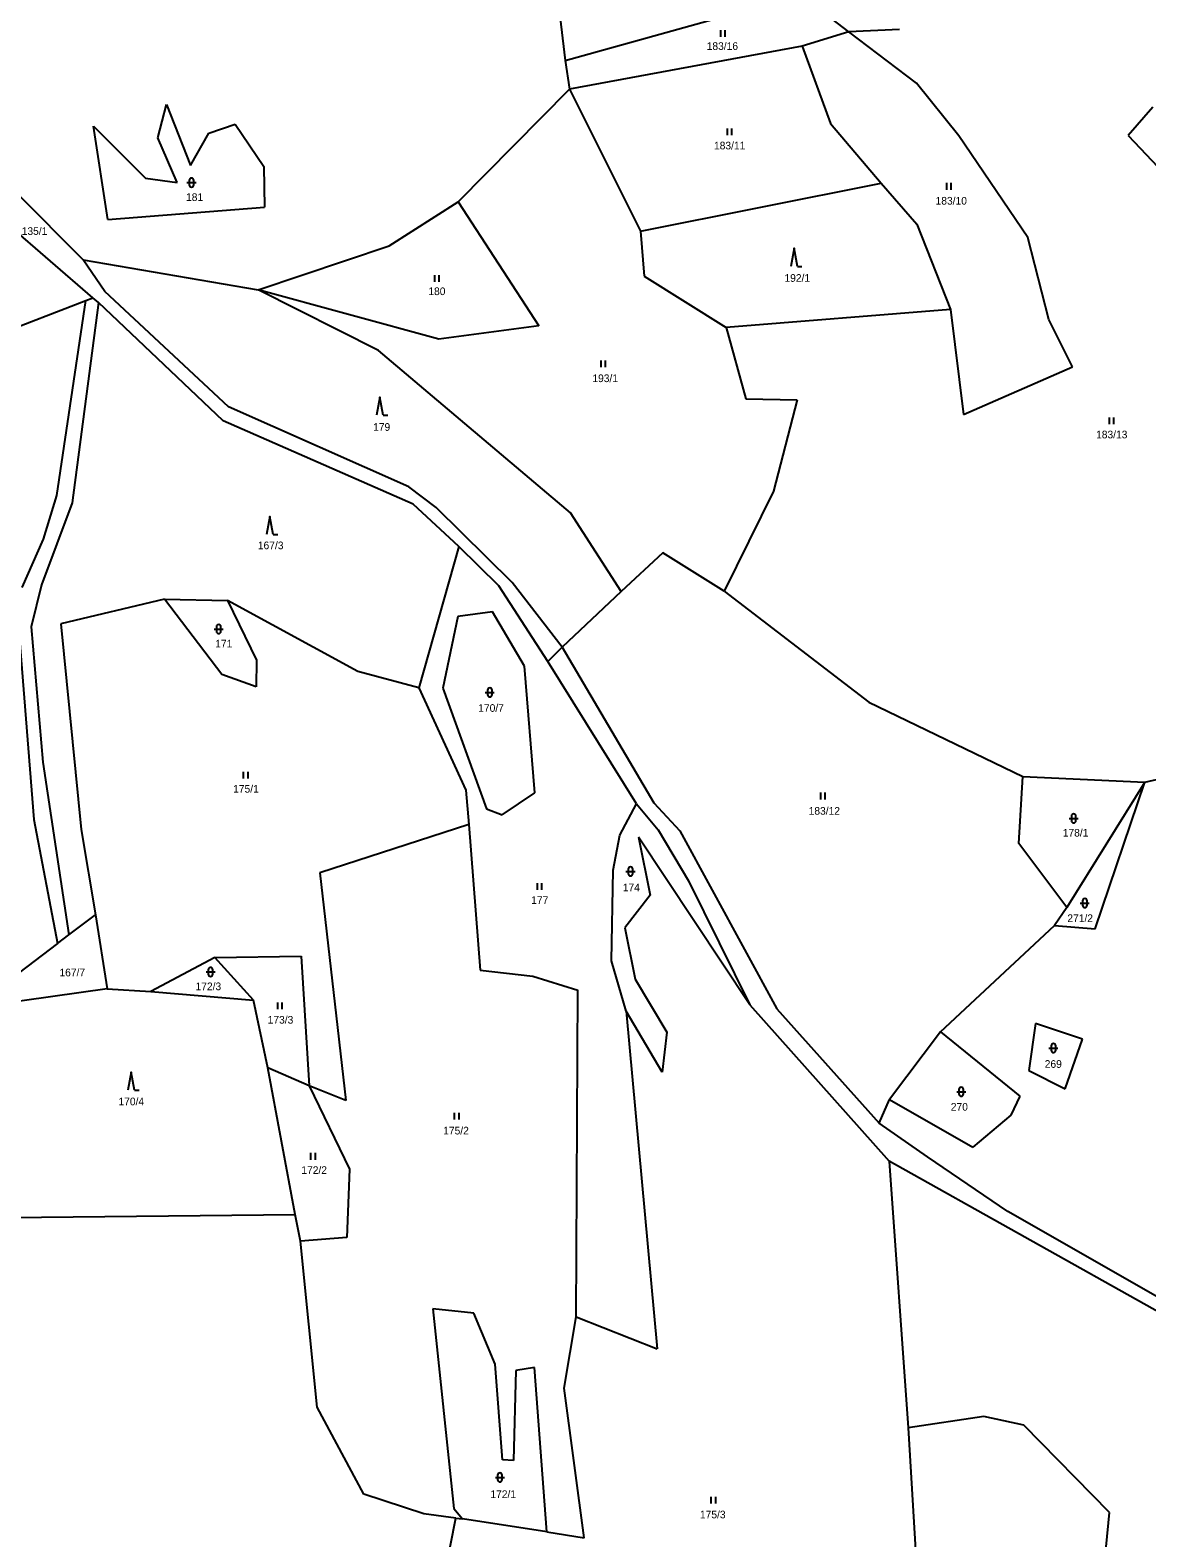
# Model space of a CAD drawing. Extents: x -765428 to -762163, y -1107632 to -1104975.
# Drawn here: x -763268.9 to -763021.2, y -1106469 to -1106134.4 of the extents above; entities that cross this region are included whole.
import ezdxf
from ezdxf.enums import TextEntityAlignment as Align

# ---------------------------------------------------------------- set-up
doc = ezdxf.new("R2010")
doc.units = 0
doc.header["$LTSCALE"] = 0.68
doc.layers.add('1', color=7, linetype='Continuous', lineweight=25)
doc.layers.add('3', color=7, linetype='Continuous', lineweight=25)
doc.layers.add('2', color=7, linetype='Continuous')

msp = doc.modelspace()

# ---------------------------------------------------------------- linework, layer by layer
at = {"layer": '1'}
for p, q in [((-763155.05, -1106100.23), (-763150.2, -1106141.11)), ((-763150.2, -1106141.11), (-763097.96, -1106126.56)), ((-763087.29, -1106134.78), (-763097.96, -1106126.56)), ((-763087.29, -1106134.78), (-763097.65, -1106137.98)), ((-763076.02, -1106134.23), (-763087.29, -1106134.78)), ((-763072.26, -1106146.15), (-763087.29, -1106134.78)), ((-763097.65, -1106137.98), (-763149.26, -1106147.51)), ((-763097.65, -1106137.98), (-763091.31, -1106155.08)), ((-763150.2, -1106141.11), (-763149.26, -1106147.51)), ((-763062.86, -1106157.85), (-763072.26, -1106146.15)), ((-763173.94, -1106172.46), (-763149.26, -1106147.51)), ((-763149.26, -1106147.51), (-763133.47, -1106179.02)), ((-763240.57, -1106158.31), (-763238.65, -1106150.92)), ((-763238.65, -1106150.92), (-763233.33, -1106164.42)), ((-763019.8, -1106151.45), (-763025.33, -1106157.75)), ((-763254.84, -1106155.68), (-763243.34, -1106167.26)), ((-763251.65, -1106176.42), (-763254.84, -1106155.68)), ((-763229.28, -1106157.25), (-763223.39, -1106155.26)), ((-763223.39, -1106155.26), (-763217.07, -1106164.63)), ((-763091.31, -1106155.08), (-763080.07, -1106168.32)), ((-763236.31, -1106168.18), (-763240.57, -1106158.31)), ((-763233.33, -1106164.42), (-763229.28, -1106157.25)), ((-763047.58, -1106180.39), (-763062.86, -1106157.85)), ((-763025.33, -1106157.75), (-763017.35, -1106166.16)), ((-763217.07, -1106164.63), (-763216.92, -1106173.65)), ((-763243.34, -1106167.26), (-763236.31, -1106168.18)), ((-763133.47, -1106179.02), (-763080.07, -1106168.32)), ((-763080.07, -1106168.32), (-763072.22, -1106177.47)), ((-763257.11, -1106185.37), (-763271.76, -1106170.68)), ((-763189.25, -1106182.29), (-763173.94, -1106172.46)), ((-763173.94, -1106172.46), (-763156.06, -1106200.02)), ((-763251.65, -1106176.42), (-763216.92, -1106173.65)), ((-763255.03, -1106193.78), (-763273.81, -1106177.51)), ((-763133.47, -1106179.02), (-763132.69, -1106189.01)), ((-763072.22, -1106177.47), (-763064.74, -1106196.39)), ((-763218.32, -1106192.01), (-763189.25, -1106182.29)), ((-763042.93, -1106198.59), (-763047.58, -1106180.39)), ((-763252.37, -1106192.42), (-763257.11, -1106185.37)), ((-763257.11, -1106185.37), (-763218.32, -1106192.01)), ((-763132.69, -1106189.01), (-763114.5, -1106200.41)), ((-763224.9, -1106218.02), (-763252.37, -1106192.42)), ((-763191.62, -1106205.5), (-763218.32, -1106192.01)), ((-763178.21, -1106202.95), (-763218.32, -1106192.01)), ((-763282.95, -1106204.58), (-763256.59, -1106194.39)), ((-763263.02, -1106237.7), (-763256.59, -1106194.39)), ((-763253.74, -1106194.87), (-763259.6, -1106239.31)), ((-763256.59, -1106194.39), (-763255.03, -1106193.78)), ((-763253.74, -1106194.87), (-763255.03, -1106193.78)), ((-763226.06, -1106221.07), (-763253.74, -1106194.87)), ((-763064.74, -1106196.39), (-763114.5, -1106200.41)), ((-763064.74, -1106196.39), (-763061.8, -1106219.73)), ((-763037.65, -1106209.11), (-763042.93, -1106198.59)), ((-763156.06, -1106200.02), (-763178.21, -1106202.95)), ((-763114.5, -1106200.41), (-763110.11, -1106216.25)), ((-763149.03, -1106241.5), (-763191.62, -1106205.5)), ((-763061.8, -1106219.73), (-763037.65, -1106209.11)), ((-763110.11, -1106216.25), (-763098.72, -1106216.45)), ((-763098.72, -1106216.45), (-763103.95, -1106236.69)), ((-763184.89, -1106235.72), (-763224.9, -1106218.02)), ((-763183.94, -1106239.57), (-763226.06, -1106221.07)), ((-763178.86, -1106240.37), (-763184.89, -1106235.72)), ((-763103.95, -1106236.69), (-763114.94, -1106258.94)), ((-763259.6, -1106239.31), (-763266.4, -1106257.48)), ((-763265.98, -1106247.33), (-763263.02, -1106237.7)), ((-763173.79, -1106248.97), (-763183.94, -1106239.57)), ((-763161.99, -1106256.99), (-763178.86, -1106240.37)), ((-763137.77, -1106259), (-763149.03, -1106241.5)), ((-763270.65, -1106258.08), (-763265.98, -1106247.33)), ((-763173.79, -1106248.97), (-763182.64, -1106280.34)), ((-763164.9, -1106257.73), (-763173.79, -1106248.97)), ((-763128.56, -1106250.38), (-763137.77, -1106259)), ((-763114.94, -1106258.94), (-763128.56, -1106250.38)), ((-763266.4, -1106257.48), (-763268.66, -1106266.83)), ((-763154.03, -1106274.53), (-763164.9, -1106257.73)), ((-763150.89, -1106271.3), (-763161.99, -1106256.99)), ((-763137.77, -1106259), (-763150.89, -1106271.3)), ((-763114.94, -1106258.94), (-763082.87, -1106283.53)), ((-763239.13, -1106260.71), (-763262.07, -1106266.13)), ((-763239.13, -1106260.71), (-763225.12, -1106260.97)), ((-763226.38, -1106277.4), (-763239.13, -1106260.71)), ((-763196.21, -1106276.75), (-763225.12, -1106260.97)), ((-763225.12, -1106260.97), (-763218.72, -1106274.19)), ((-763166.36, -1106263.48), (-763174.01, -1106264.52)), ((-763159.21, -1106275.53), (-763166.36, -1106263.48)), ((-763271.65, -1106264.9), (-763268.06, -1106309.55)), ((-763268.66, -1106266.83), (-763266.06, -1106296.83)), ((-763262.07, -1106266.13), (-763257.62, -1106311.79)), ((-763174.01, -1106264.52), (-763177.36, -1106280.42)), ((-763154.03, -1106274.53), (-763150.89, -1106271.3)), ((-763150.89, -1106271.3), (-763130.53, -1106305.89)), ((-763218.72, -1106274.19), (-763218.8, -1106280.14)), ((-763182.64, -1106280.34), (-763196.21, -1106276.75)), ((-763156.95, -1106303.63), (-763159.21, -1106275.53)), ((-763134.35, -1106306.07), (-763154.03, -1106274.53)), ((-763218.8, -1106280.14), (-763226.38, -1106277.4)), ((-763182.64, -1106280.34), (-763172.26, -1106303.06)), ((-763177.36, -1106280.42), (-763167.65, -1106307.24)), ((-763082.87, -1106283.53), (-763048.67, -1106300.02)), ((-763266.06, -1106296.83), (-763260.29, -1106335.2)), ((-763049.56, -1106314.94), (-763048.67, -1106300.02)), ((-763048.67, -1106300.02), (-763021.57, -1106301.33)), ((-763021.57, -1106301.33), (-763011.94, -1106299.02)), ((-763172.26, -1106303.06), (-763171.59, -1106310.7)), ((-763164.15, -1106308.58), (-763156.95, -1106303.63)), ((-763021.57, -1106301.33), (-763038.92, -1106329.08)), ((-763032.65, -1106333.85), (-763021.57, -1106301.33)), ((-763138.06, -1106313.08), (-763134.35, -1106306.07)), ((-763134.35, -1106306.07), (-763129.6, -1106311.86)), ((-763130.53, -1106305.89), (-763124.76, -1106312.1)), ((-763268.06, -1106309.55), (-763262.82, -1106337.09)), ((-763167.65, -1106307.24), (-763164.15, -1106308.58)), ((-763257.62, -1106311.79), (-763254.43, -1106330.76)), ((-763171.59, -1106310.7), (-763204.65, -1106321.44)), ((-763171.59, -1106310.7), (-763169.07, -1106343.02)), ((-763139.56, -1106320.84), (-763138.06, -1106313.08)), ((-763109.27, -1106350.74), (-763133.95, -1106313.48)), ((-763133.95, -1106313.48), (-763131.37, -1106326.39)), ((-763129.6, -1106311.86), (-763122.82, -1106323.16)), ((-763124.76, -1106312.1), (-763103.23, -1106351.63)), ((-763038.92, -1106329.08), (-763049.56, -1106314.94)), ((-763204.65, -1106321.44), (-763198.84, -1106371.92)), ((-763139.91, -1106340.95), (-763139.56, -1106320.84)), ((-763122.82, -1106323.16), (-763109.27, -1106350.74)), ((-763131.37, -1106326.39), (-763136.98, -1106333.59)), ((-763038.92, -1106329.08), (-763041.67, -1106333.13)), ((-763260.29, -1106335.2), (-763254.43, -1106330.76)), ((-763254.43, -1106330.76), (-763251.8, -1106347.17)), ((-763136.98, -1106333.59), (-763134.64, -1106344.99)), ((-763066.91, -1106356.7), (-763041.67, -1106333.13)), ((-763041.67, -1106333.13), (-763032.65, -1106333.85)), ((-763262.82, -1106337.09), (-763283.96, -1106353.12)), ((-763262.82, -1106337.09), (-763260.29, -1106335.2)), ((-763227.96, -1106340.23), (-763242.12, -1106347.79)), ((-763227.96, -1106340.23), (-763208.75, -1106339.9)), ((-763219.39, -1106349.65), (-763227.96, -1106340.23)), ((-763208.75, -1106339.9), (-763207.04, -1106368.71)), ((-763169.07, -1106343.02), (-763157.36, -1106344.33)), ((-763136.7, -1106352.1), (-763139.91, -1106340.95)), ((-763251.8, -1106347.17), (-763277.09, -1106350.73)), ((-763251.8, -1106347.17), (-763242.12, -1106347.79)), ((-763157.36, -1106344.33), (-763147.4, -1106347.43)), ((-763134.64, -1106344.99), (-763127.64, -1106356.77)), ((-763242.12, -1106347.79), (-763219.39, -1106349.65)), ((-763216.18, -1106364.7), (-763219.39, -1106349.65)), ((-763147.79, -1106419.95), (-763147.4, -1106347.43)), ((-763128.66, -1106365.65), (-763136.7, -1106352.1)), ((-763136.7, -1106352.1), (-763129.81, -1106427.03)), ((-763109.27, -1106350.74), (-763078.33, -1106385.39)), ((-763103.23, -1106351.63), (-763080.56, -1106377.01)), ((-763127.64, -1106356.77), (-763128.66, -1106365.65)), ((-763066.91, -1106356.7), (-763078.26, -1106371.73)), ((-763066.91, -1106356.7), (-763049.34, -1106371.02)), ((-763045.85, -1106354.84), (-763047.33, -1106365.28)), ((-763035.4, -1106358.33), (-763045.85, -1106354.84)), ((-763039.27, -1106369.33), (-763035.4, -1106358.33)), ((-763210.08, -1106397.22), (-763216.18, -1106364.7)), ((-763207.04, -1106368.71), (-763216.18, -1106364.7)), ((-763047.33, -1106365.28), (-763039.27, -1106369.33)), ((-763207.04, -1106368.71), (-763198.08, -1106387.18)), ((-763198.84, -1106371.92), (-763207.04, -1106368.71)), ((-763080.56, -1106377.01), (-763078.26, -1106371.73)), ((-763078.26, -1106371.73), (-763059.79, -1106382.33)), ((-763049.34, -1106371.02), (-763051.34, -1106375.17)), ((-763069.84, -1106384.46), (-763080.56, -1106377.01)), ((-763051.34, -1106375.17), (-763059.79, -1106382.33)), ((-763198.08, -1106387.18), (-763198.64, -1106402.39)), ((-763052.02, -1106396.62), (-763069.84, -1106384.46)), ((-763273.44, -1106397.91), (-763210.08, -1106397.22)), ((-763208.96, -1106403.17), (-763210.08, -1106397.22)), ((-763015.12, -1106417.7), (-763052.02, -1106396.62)), ((-763198.64, -1106402.39), (-763208.96, -1106403.17)), ((-763205.2, -1106440.01), (-763208.96, -1106403.17)), ((-763179.58, -1106418.2), (-763174.89, -1106462.52)), ((-763170.46, -1106419.17), (-763179.58, -1106418.2)), ((-763165.77, -1106430.47), (-763170.46, -1106419.17)), ((-763150.45, -1106435.8), (-763147.79, -1106419.95)), ((-763147.79, -1106419.95), (-763129.81, -1106427.03)), ((-763164.1, -1106451.73), (-763165.77, -1106430.47)), ((-763161.15, -1106431.88), (-763161.66, -1106451.86)), ((-763157.04, -1106431.18), (-763161.15, -1106431.88)), ((-763154.28, -1106467.66), (-763157.04, -1106431.18)), ((-763145.98, -1106468.98), (-763150.45, -1106435.8)), ((-763194.88, -1106459.35), (-763205.2, -1106440.01)), ((-763057.32, -1106442.1), (-763074.11, -1106444.61)), ((-763048.42, -1106444.04), (-763057.32, -1106442.1)), ((-763029.44, -1106463.4), (-763048.42, -1106444.04)), ((-763074.11, -1106444.61), (-763072.15, -1106477.08)), ((-763161.66, -1106451.86), (-763164.1, -1106451.73)), ((-763181.53, -1106463.69), (-763194.88, -1106459.35)), ((-763174.46, -1106464.63), (-763181.53, -1106463.69)), ((-763174.89, -1106462.52), (-763172.96, -1106464.83)), ((-763030.2, -1106471.03), (-763029.44, -1106463.4)), ((-763177.79, -1106481.32), (-763174.46, -1106464.63)), ((-763174.46, -1106464.63), (-763172.96, -1106464.83)), ((-763154.28, -1106467.66), (-763172.96, -1106464.83)), ((-763154.28, -1106467.66), (-763145.98, -1106468.98))]:
    msp.add_line(p, q, dxfattribs=at)
msp.add_lwpolyline([(-763018.11, -1106419.15), (-763078.33, -1106385.39), (-763074.11, -1106444.61)], dxfattribs=at)
at = {"layer": '3'}
for p, q in [((-763115.701, -1106135.9), (-763115.701, -1106134.4)), ((-763114.7, -1106135.9), (-763114.7, -1106134.4)), ((-763114.221, -1106157.73), (-763114.221, -1106156.23)), ((-763113.22, -1106157.73), (-763113.22, -1106156.23)), ((-763234.111, -1106168.231), (-763232.109, -1106168.231)), ((-763233.611, -1106167.731), (-763233.611, -1106168.732)), ((-763232.609, -1106168.732), (-763232.609, -1106167.731)), ((-763065.561, -1106169.81), (-763065.561, -1106168.31)), ((-763064.56, -1106169.81), (-763064.56, -1106168.31)), ((-763179.151, -1106190.27), (-763179.151, -1106188.77)), ((-763178.15, -1106190.27), (-763178.15, -1106188.77)), ((-763098.67, -1106186.81), (-763097.674, -1106186.81)), ((-763142.231, -1106209.18), (-763142.231, -1106207.68)), ((-763141.23, -1106209.18), (-763141.23, -1106207.68)), ((-763190.55, -1106219.87), (-763189.554, -1106219.87)), ((-763029.451, -1106221.86), (-763029.451, -1106220.36)), ((-763028.45, -1106221.86), (-763028.45, -1106220.36)), ((-763214.97, -1106246.3), (-763213.974, -1106246.3)), ((-763227.571, -1106266.811), (-763227.571, -1106267.812)), ((-763226.569, -1106267.812), (-763226.569, -1106266.811)), ((-763228.071, -1106267.311), (-763226.069, -1106267.311)), ((-763167.931, -1106281.371), (-763165.929, -1106281.371)), ((-763167.431, -1106280.871), (-763167.431, -1106281.872)), ((-763166.429, -1106281.872), (-763166.429, -1106280.871)), ((-763221.541, -1106300.5), (-763221.541, -1106299)), ((-763220.54, -1106300.5), (-763220.54, -1106299)), ((-763093.501, -1106305.12), (-763093.501, -1106303.62)), ((-763092.5, -1106305.12), (-763092.5, -1106303.62)), ((-763038.391, -1106309.341), (-763036.389, -1106309.341)), ((-763037.891, -1106308.841), (-763037.891, -1106309.842)), ((-763036.889, -1106309.842), (-763036.889, -1106308.841)), ((-763156.351, -1106325.2), (-763156.351, -1106323.7)), ((-763155.35, -1106325.2), (-763155.35, -1106323.7)), ((-763136.711, -1106321.111), (-763134.709, -1106321.111)), ((-763136.211, -1106320.611), (-763136.211, -1106321.612)), ((-763135.209, -1106321.612), (-763135.209, -1106320.611)), ((-763035.921, -1106328.131), (-763033.919, -1106328.131)), ((-763035.421, -1106327.631), (-763035.421, -1106328.632)), ((-763034.419, -1106328.632), (-763034.419, -1106327.631)), ((-763229.881, -1106343.411), (-763227.879, -1106343.411)), ((-763229.381, -1106342.911), (-763229.381, -1106343.912)), ((-763228.379, -1106343.912), (-763228.379, -1106342.911)), ((-763213.991, -1106351.7), (-763213.991, -1106350.2)), ((-763212.99, -1106351.7), (-763212.99, -1106350.2)), ((-763042.881, -1106360.311), (-763040.879, -1106360.311)), ((-763042.381, -1106359.811), (-763042.381, -1106360.812)), ((-763041.379, -1106360.812), (-763041.379, -1106359.811)), ((-763245.72, -1106369.63), (-763244.724, -1106369.63)), ((-763063.331, -1106369.991), (-763061.329, -1106369.991)), ((-763062.831, -1106369.491), (-763062.831, -1106370.492)), ((-763061.829, -1106370.492), (-763061.829, -1106369.491)), ((-763174.731, -1106376.19), (-763174.731, -1106374.69)), ((-763173.73, -1106376.19), (-763173.73, -1106374.69)), ((-763206.621, -1106385.09), (-763206.621, -1106383.59)), ((-763205.62, -1106385.09), (-763205.62, -1106383.59)), ((-763165.691, -1106455.601), (-763163.689, -1106455.601)), ((-763165.191, -1106455.101), (-763165.191, -1106456.102)), ((-763164.189, -1106456.102), (-763164.189, -1106455.101)), ((-763117.781, -1106461.4), (-763117.781, -1106459.9)), ((-763116.78, -1106461.4), (-763116.78, -1106459.9))]:
    msp.add_line(p, q, dxfattribs=at)
for points in [[(-763098.67, -1106186.81), (-763099.42, -1106182.81), (-763100.17, -1106186.81)], [(-763190.55, -1106219.87), (-763191.3, -1106215.87), (-763192.05, -1106219.87)], [(-763214.97, -1106246.3), (-763215.72, -1106242.3), (-763216.47, -1106246.3)], [(-763245.72, -1106369.63), (-763246.47, -1106365.63), (-763247.22, -1106369.63)]]:
    msp.add_lwpolyline(points, dxfattribs=at)
for centre, start, end in [((-763233.11, -1106167.7309), 0, 180), ((-763233.11, -1106168.7309), 180, 359.98789), ((-763227.07, -1106266.8109), 0, 180), ((-763227.07, -1106267.8109), 180, 359.98789), ((-763166.93, -1106280.8709), 0, 180), ((-763166.93, -1106281.8709), 180, 359.98789), ((-763037.39, -1106308.8409), 0, 180), ((-763037.39, -1106309.8409), 180, 359.98789), ((-763135.71, -1106320.6109), 0, 180), ((-763135.71, -1106321.6109), 180, 359.98789), ((-763034.92, -1106327.6309), 0, 180), ((-763034.92, -1106328.6309), 180, 359.98789), ((-763228.88, -1106342.9109), 0, 180), ((-763228.88, -1106343.9109), 180, 359.98789), ((-763041.88, -1106359.8109), 0, 180), ((-763041.88, -1106360.8109), 180, 359.98789), ((-763062.33, -1106369.4909), 0, 180), ((-763062.33, -1106370.4909), 180, 359.98789), ((-763164.69, -1106455.1009), 0, 180), ((-763164.69, -1106456.1009), 180, 359.98789)]:
    msp.add_arc(centre, 0.5, start, end, dxfattribs=at)

# ---------------------------------------------------------------- texts
at = {"layer": '2'}
for s, p in [('183/16', (-763115.33, -1106138.775)), ('183/11', (-763113.71, -1106160.855)), ('183/10', (-763064.55, -1106173.105)), ('1135/1', (-763268.57, -1106179.835)), ('183/13', (-763028.94, -1106224.985)), ('175/1', (-763221.03, -1106303.625)), ('183/12', (-763092.71, -1106308.515)), ('177', (-763155.839, -1106328.325)), ('170/4', (-763246.47, -1106373.015)), ('175/2', (-763174.42, -1106379.485)), ('175/3', (-763117.46, -1106464.685))]:
    msp.add_text(s, height=1.7, dxfattribs=at).set_placement(p, align=Align.CENTER)
for s, p in [('181', (-763234.32, -1106172.305)), ('192/1', (-763101.56, -1106190.245)), ('180', (-763180.56, -1106193.195)), ('193/1', (-763144.17, -1106212.505)), ('179', (-763192.81, -1106223.315)), ('167/3', (-763218.39, -1106249.595)), ('171', (-763227.84, -1106271.405)), ('170/7', (-763169.49, -1106285.685)), ('178/1', (-763039.81, -1106313.375)), ('174', (-763137.42, -1106325.515)), ('271/2', (-763038.79, -1106332.335)), ('167/7', (-763262.41, -1106344.385)), ('172/3', (-763232.21, -1106347.465)), ('173/3', (-763216.21, -1106354.885)), ('269', (-763043.81, -1106364.695)), ('270', (-763064.65, -1106374.205)), ('172/2', (-763208.74, -1106388.245)), ('172/1', (-763166.8, -1106460.175))]:
    msp.add_text(s, height=1.7, dxfattribs=at).set_placement(p)

doc.saveas('drawing.dxf')
